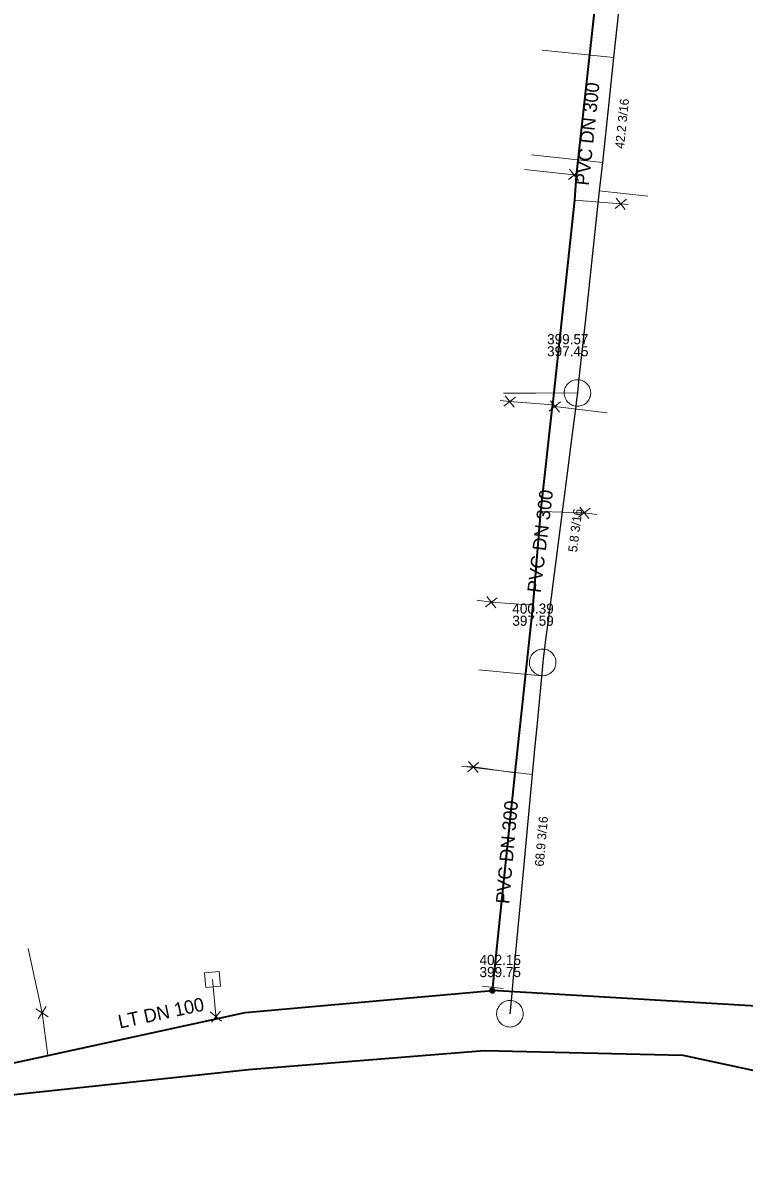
# Model space of a CAD drawing. Extents: x -772952 to -772403, y -1033777 to -1033210.
# Drawn here: x -772746.2 to -772682, y -1033603.9 to -1033502.9 of the extents above; entities that cross this region are included whole.
import ezdxf

# ---------------------------------------------------------------- set-up
doc = ezdxf.new("R2010")
doc.units = 0
doc.header["$LTSCALE"] = 0.36
for name, color, linetype, lineweight in [('15', 7, 'Continuous', 13), ('16', 7, 'Continuous', 35), ('2', 7, 'Continuous', 25), ('21', 7, 'Continuous', 13), ('4', 7, 'Continuous', 13), ('57', 7, 'Continuous', 13), ('59', 7, 'Continuous', 13)]:
    doc.layers.add(name, color=color, linetype=linetype, lineweight=lineweight)
for name, color, linetype in [('17', 7, 'Continuous'), ('3', 7, 'Continuous'), ('6', 7, 'Continuous')]:
    doc.layers.add(name, color=color, linetype=linetype)

msp = doc.modelspace()

# ---------------------------------------------------------------- linework, layer by layer
at = {"layer": '15'}
for p, q in [((-772696.643, -1033515.992), (-772697.658, -1033516.807)), ((-772696.747, -1033516.901), (-772697.552, -1033515.893)), ((-772693.507, -1033519.381), (-772692.502, -1033518.554)), ((-772693.414, -1033518.471), (-772692.596, -1033519.469)), ((-772702.369, -1033536.129), (-772703.392, -1033536.934)), ((-772702.482, -1033537.037), (-772703.278, -1033536.021)), ((-772699.365, -1033537.378), (-772698.344, -1033536.571)), ((-772699.254, -1033536.47), (-772698.456, -1033537.484)), ((-772696.757, -1033546.813), (-772695.726, -1033546.018)), ((-772696.635, -1033545.906), (-772695.85, -1033546.93)), ((-772703.991, -1033553.966), (-772705.024, -1033554.757)), ((-772704.116, -1033554.872), (-772704.898, -1033553.846)), ((-772705.61, -1033568.566), (-772706.589, -1033569.425)), ((-772705.675, -1033569.479), (-772706.523, -1033568.507)), ((-772703.459, -1033588.692), (-772705.309, -1033588.473)), ((-772743.894, -1033591.191), (-772744.987, -1033590.484)), ((-772744.79, -1033591.379), (-772744.087, -1033590.297)), ((-772728.485, -1033591.6), (-772729.487, -1033590.769)), ((-772729.396, -1033591.681), (-772728.57, -1033590.689))]:
    msp.add_line(p, q, dxfattribs=at)
for points in [[(-772704.19, -1033588.864), (-772704.196, -1033588.812), (-772704.213, -1033588.762), (-772704.242, -1033588.718), (-772704.279, -1033588.681), (-772704.324, -1033588.654), (-772704.374, -1033588.637), (-772704.427, -1033588.633), (-772704.478, -1033588.64), (-772704.527, -1033588.659), (-772704.571, -1033588.688), (-772704.607, -1033588.727), (-772704.633, -1033588.772), (-772704.649, -1033588.823), (-772704.652, -1033588.875), (-772704.644, -1033588.927), (-772704.624, -1033588.976), (-772704.593, -1033589.019), (-772704.554, -1033589.053), (-772704.508, -1033589.079), (-772704.456, -1033589.093), (-772704.404, -1033589.095), (-772704.353, -1033589.085), (-772704.304, -1033589.064), (-772704.262, -1033589.033), (-772704.228, -1033588.992), (-772704.204, -1033588.946), (-772704.191, -1033588.895)], [(-772704.22, -1033588.864), (-772704.226, -1033588.815), (-772704.243, -1033588.769), (-772704.271, -1033588.729), (-772704.308, -1033588.697), (-772704.352, -1033588.675), (-772704.4, -1033588.664), (-772704.449, -1033588.664), (-772704.495, -1033588.677), (-772704.539, -1033588.701), (-772704.575, -1033588.734), (-772704.602, -1033588.775), (-772704.618, -1033588.822), (-772704.622, -1033588.871), (-772704.615, -1033588.919), (-772704.596, -1033588.964), (-772704.566, -1033589.004), (-772704.527, -1033589.035), (-772704.483, -1033589.055), (-772704.436, -1033589.065), (-772704.387, -1033589.063), (-772704.34, -1033589.048), (-772704.297, -1033589.023), (-772704.262, -1033588.989), (-772704.237, -1033588.947), (-772704.223, -1033588.9)], [(-772704.25, -1033588.864), (-772704.255, -1033588.819), (-772704.272, -1033588.777), (-772704.301, -1033588.742), (-772704.337, -1033588.715), (-772704.379, -1033588.698), (-772704.424, -1033588.693), (-772704.468, -1033588.699), (-772704.51, -1033588.718), (-772704.544, -1033588.746), (-772704.571, -1033588.783), (-772704.588, -1033588.825), (-772704.592, -1033588.87), (-772704.585, -1033588.915), (-772704.566, -1033588.956), (-772704.537, -1033588.99), (-772704.5, -1033589.016), (-772704.456, -1033589.032), (-772704.412, -1033589.035), (-772704.367, -1033589.027), (-772704.326, -1033589.007), (-772704.293, -1033588.978), (-772704.267, -1033588.94), (-772704.253, -1033588.897)], [(-772704.28, -1033588.864), (-772704.284, -1033588.823), (-772704.303, -1033588.786), (-772704.33, -1033588.755), (-772704.365, -1033588.734), (-772704.405, -1033588.723), (-772704.446, -1033588.725), (-772704.485, -1033588.738), (-772704.519, -1033588.762), (-772704.544, -1033588.794), (-772704.559, -1033588.832), (-772704.561, -1033588.873), (-772704.554, -1033588.913), (-772704.534, -1033588.949), (-772704.505, -1033588.978), (-772704.468, -1033588.997), (-772704.428, -1033589.005), (-772704.387, -1033589.001), (-772704.348, -1033588.986), (-772704.316, -1033588.96), (-772704.294, -1033588.926), (-772704.281, -1033588.887)], [(-772704.309, -1033588.864), (-772704.315, -1033588.828), (-772704.333, -1033588.796), (-772704.358, -1033588.771), (-772704.392, -1033588.756), (-772704.429, -1033588.753), (-772704.463, -1033588.761), (-772704.495, -1033588.781), (-772704.517, -1033588.809), (-772704.531, -1033588.843), (-772704.531, -1033588.88), (-772704.52, -1033588.915), (-772704.499, -1033588.944), (-772704.468, -1033588.965), (-772704.434, -1033588.975), (-772704.397, -1033588.973), (-772704.363, -1033588.959), (-772704.336, -1033588.936), (-772704.316, -1033588.904), (-772704.309, -1033588.869)], [(-772704.34, -1033588.864), (-772704.345, -1033588.833), (-772704.362, -1033588.807), (-772704.387, -1033588.79), (-772704.418, -1033588.783), (-772704.449, -1033588.787), (-772704.476, -1033588.804), (-772704.494, -1033588.828), (-772704.502, -1033588.859), (-772704.498, -1033588.889), (-772704.483, -1033588.917), (-772704.458, -1033588.936), (-772704.429, -1033588.945), (-772704.397, -1033588.942), (-772704.37, -1033588.928), (-772704.35, -1033588.904), (-772704.34, -1033588.875)], [(-772704.37, -1033588.864), (-772704.375, -1033588.84), (-772704.392, -1033588.822), (-772704.414, -1033588.813), (-772704.439, -1033588.816), (-772704.46, -1033588.83), (-772704.471, -1033588.852), (-772704.471, -1033588.877), (-772704.458, -1033588.898), (-772704.439, -1033588.912), (-772704.414, -1033588.915), (-772704.391, -1033588.906), (-772704.375, -1033588.888)], [(-772704.4, -1033588.864), (-772704.405, -1033588.849), (-772704.419, -1033588.843), (-772704.434, -1033588.847), (-772704.441, -1033588.861), (-772704.438, -1033588.876), (-772704.424, -1033588.885), (-772704.409, -1033588.882), (-772704.4, -1033588.87)]]:
    msp.add_lwpolyline(points, close=True, dxfattribs=at)
at = {"layer": '16'}
msp.add_line((-772704.383, -1033588.583), (-772704.421, -1033588.864), dxfattribs=at)
for points in [[(-772704.383, -1033588.583), (-772702.394, -1033569.524), (-772700.793, -1033554.627), (-772700.105, -1033546.293), (-772699.07, -1033536.936), (-772699.052, -1033536.82), (-772697.087, -1033518.651), (-772696.925, -1033516.445), (-772694.923, -1033498.129)], [(-772871.839, -1033575.434), (-772870.427, -1033576.155), (-772849.008, -1033581.096), (-772841.55, -1033584.107), (-772822.87, -1033596.07), (-772815.517, -1033599.879), (-772800.324, -1033602.374), (-772785.625, -1033603.857), (-772759.69, -1033599.467), (-772726.1, -1033595.877), (-772705.133, -1033594.197), (-772687.467, -1033594.611), (-772649.087, -1033602.85)], [(-772759.272, -1033597.956), (-772743.932, -1033594.627), (-772726.379, -1033590.82), (-772704.421, -1033588.864)], [(-772638.76, -1033596.131), (-772655.276, -1033593.796), (-772676.921, -1033590.5), (-772704.421, -1033588.864)]]:
    msp.add_lwpolyline(points, dxfattribs=at)
at = {"layer": '2'}
for points in [[(-772691.61, -1033487.27), (-772691.649, -1033487.634), (-772691.677, -1033487.891), (-772691.701, -1033488.118), (-772691.747, -1033488.542), (-772692.035, -1033491.203), (-772692.309, -1033493.741), (-772693.008, -1033500.216), (-772693.63, -1033505.97), (-772694.06, -1033509.95), (-772694.633, -1033515.304), (-772694.908, -1033517.801), (-772695.388, -1033522.246), (-772696.055, -1033528.415), (-772696.596, -1033533.419), (-772696.742, -1033534.772), (-772696.85, -1033535.77)], [(-772696.85, -1033535.77), (-772696.902, -1033536.175), (-772696.961, -1033536.631), (-772697.003, -1033536.959), (-772697.141, -1033538.027), (-772697.469, -1033540.57), (-772697.77, -1033542.899), (-772698.506, -1033548.607), (-772699.46, -1033555.994), (-772699.675, -1033557.662), (-772699.776, -1033558.443), (-772699.839, -1033558.931), (-772699.863, -1033559.117), (-772699.94, -1033559.71)], [(-772699.94, -1033559.71), (-772700.444, -1033565.106), (-772700.66, -1033567.424), (-772700.869, -1033569.664), (-772701.647, -1033577.994), (-772702.461, -1033586.7), (-772702.748, -1033589.781), (-772702.855, -1033590.926)]]:
    msp.add_lwpolyline(points, dxfattribs=at)
at = {"layer": '21'}
msp.add_lwpolyline([(-772729.886, -1033588.595), (-772728.58, -1033588.473), (-772728.703, -1033587.167), (-772730.009, -1033587.289)], close=True, dxfattribs=at)
at = {"layer": '4'}
for points in [[(-772695.669, -1033535.77), (-772695.676, -1033535.651), (-772695.694, -1033535.534), (-772695.723, -1033535.418), (-772695.764, -1033535.307), (-772695.816, -1033535.2), (-772695.879, -1033535.099), (-772695.951, -1033535.004), (-772696.032, -1033534.918), (-772696.123, -1033534.84), (-772696.221, -1033534.771), (-772696.324, -1033534.713), (-772696.433, -1033534.666), (-772696.547, -1033534.629), (-772696.663, -1033534.604), (-772696.781, -1033534.592), (-772696.9, -1033534.591), (-772697.019, -1033534.602), (-772697.135, -1033534.625), (-772697.249, -1033534.659), (-772697.358, -1033534.705), (-772697.463, -1033534.762), (-772697.562, -1033534.829), (-772697.652, -1033534.905), (-772697.736, -1033534.99), (-772697.809, -1033535.084), (-772697.874, -1033535.184), (-772697.928, -1033535.29), (-772697.971, -1033535.401), (-772698.003, -1033535.515), (-772698.022, -1033535.633), (-772698.03, -1033535.752), (-772698.026, -1033535.87), (-772698.01, -1033535.988), (-772697.982, -1033536.104), (-772697.943, -1033536.216), (-772697.892, -1033536.324), (-772697.831, -1033536.426), (-772697.76, -1033536.522), (-772697.679, -1033536.609), (-772697.591, -1033536.689), (-772697.495, -1033536.759), (-772697.392, -1033536.819), (-772697.284, -1033536.868), (-772697.171, -1033536.906), (-772697.054, -1033536.932), (-772696.937, -1033536.947), (-772696.818, -1033536.95), (-772696.7, -1033536.941), (-772696.581, -1033536.92), (-772696.468, -1033536.887), (-772696.358, -1033536.843), (-772696.252, -1033536.788), (-772696.152, -1033536.722), (-772696.059, -1033536.647), (-772695.976, -1033536.563), (-772695.901, -1033536.471), (-772695.835, -1033536.372), (-772695.779, -1033536.267), (-772695.735, -1033536.157), (-772695.701, -1033536.043), (-772695.679, -1033535.926), (-772695.669, -1033535.807)], [(-772698.759, -1033559.71), (-772698.766, -1033559.591), (-772698.784, -1033559.474), (-772698.813, -1033559.358), (-772698.853, -1033559.247), (-772698.906, -1033559.14), (-772698.968, -1033559.039), (-772699.041, -1033558.944), (-772699.122, -1033558.858), (-772699.213, -1033558.78), (-772699.311, -1033558.711), (-772699.414, -1033558.653), (-772699.522, -1033558.606), (-772699.637, -1033558.569), (-772699.752, -1033558.544), (-772699.87, -1033558.532), (-772699.99, -1033558.531), (-772700.108, -1033558.542), (-772700.225, -1033558.565), (-772700.338, -1033558.599), (-772700.448, -1033558.645), (-772700.553, -1033558.702), (-772700.652, -1033558.769), (-772700.742, -1033558.845), (-772700.826, -1033558.93), (-772700.899, -1033559.024), (-772700.963, -1033559.124), (-772701.017, -1033559.23), (-772701.061, -1033559.341), (-772701.093, -1033559.455), (-772701.112, -1033559.573), (-772701.12, -1033559.692), (-772701.115, -1033559.81), (-772701.1, -1033559.928), (-772701.071, -1033560.044), (-772701.032, -1033560.156), (-772700.982, -1033560.264), (-772700.921, -1033560.366), (-772700.85, -1033560.462), (-772700.769, -1033560.549), (-772700.681, -1033560.629), (-772700.585, -1033560.699), (-772700.482, -1033560.759), (-772700.374, -1033560.808), (-772700.261, -1033560.846), (-772700.144, -1033560.872), (-772700.027, -1033560.887), (-772699.907, -1033560.89), (-772699.789, -1033560.881), (-772699.671, -1033560.86), (-772699.558, -1033560.827), (-772699.448, -1033560.783), (-772699.342, -1033560.728), (-772699.242, -1033560.662), (-772699.149, -1033560.587), (-772699.066, -1033560.503), (-772698.99, -1033560.411), (-772698.924, -1033560.312), (-772698.869, -1033560.207), (-772698.825, -1033560.097), (-772698.791, -1033559.983), (-772698.769, -1033559.866), (-772698.759, -1033559.747)], [(-772701.674, -1033590.926), (-772701.681, -1033590.807), (-772701.699, -1033590.69), (-772701.728, -1033590.574), (-772701.769, -1033590.463), (-772701.821, -1033590.356), (-772701.884, -1033590.255), (-772701.956, -1033590.16), (-772702.038, -1033590.074), (-772702.128, -1033589.996), (-772702.226, -1033589.927), (-772702.329, -1033589.869), (-772702.438, -1033589.822), (-772702.552, -1033589.785), (-772702.668, -1033589.76), (-772702.786, -1033589.748), (-772702.905, -1033589.747), (-772703.024, -1033589.758), (-772703.14, -1033589.781), (-772703.254, -1033589.815), (-772703.364, -1033589.861), (-772703.468, -1033589.918), (-772703.567, -1033589.985), (-772703.657, -1033590.061), (-772703.741, -1033590.146), (-772703.815, -1033590.24), (-772703.879, -1033590.34), (-772703.933, -1033590.446), (-772703.976, -1033590.557), (-772704.008, -1033590.671), (-772704.027, -1033590.789), (-772704.035, -1033590.908), (-772704.031, -1033591.026), (-772704.015, -1033591.144), (-772703.987, -1033591.26), (-772703.948, -1033591.372), (-772703.897, -1033591.48), (-772703.836, -1033591.582), (-772703.765, -1033591.678), (-772703.684, -1033591.765), (-772703.596, -1033591.845), (-772703.5, -1033591.915), (-772703.397, -1033591.975), (-772703.289, -1033592.024), (-772703.176, -1033592.062), (-772703.059, -1033592.088), (-772702.942, -1033592.103), (-772702.823, -1033592.106), (-772702.705, -1033592.097), (-772702.587, -1033592.076), (-772702.473, -1033592.043), (-772702.363, -1033591.999), (-772702.257, -1033591.944), (-772702.157, -1033591.878), (-772702.065, -1033591.803), (-772701.981, -1033591.719), (-772701.906, -1033591.627), (-772701.84, -1033591.528), (-772701.784, -1033591.423), (-772701.74, -1033591.313), (-772701.706, -1033591.199), (-772701.684, -1033591.082), (-772701.674, -1033590.963)]]:
    msp.add_lwpolyline(points, close=True, dxfattribs=at)
at = {"layer": '57'}
for p, q in [((-772693.63, -1033505.97), (-772699.98, -1033505.3)), ((-772694.633, -1033515.304), (-772700.92, -1033514.6)), ((-772694.908, -1033517.801), (-772690.59, -1033518.27)), ((-772700.051, -1033560.906), (-772705.61, -1033560.36)), ((-772700.869, -1033569.664), (-772706.64, -1033569))]:
    msp.add_line(p, q, dxfattribs=at)
msp.add_lwpolyline([(-772696.85, -1033535.77), (-772700.592, -1033535.784), (-772703.432, -1033535.795)], dxfattribs=at)
at = {"layer": '59'}
msp.add_line((-772728.967, -1033591.381), (-772729.295, -1033587.881), dxfattribs=at)
for points in [[(-772696.926, -1033516.446), (-772697.15, -1033516.399), (-772701.552, -1033515.918)], [(-772697.088, -1033518.651), (-772693.006, -1033518.969), (-772692.354, -1033519.032)], [(-772699.052, -1033536.821), (-772702.88, -1033536.531), (-772703.716, -1033536.432)], [(-772699.069, -1033536.936), (-772698.856, -1033536.976), (-772694.195, -1033537.521)], [(-772700.106, -1033546.294), (-772696.243, -1033546.417), (-772695.136, -1033546.56)], [(-772700.794, -1033554.628), (-772704.507, -1033554.361), (-772705.802, -1033554.19)], [(-772702.394, -1033569.525), (-772706.099, -1033568.995), (-772707.145, -1033568.927)], [(-772743.932, -1033594.627), (-772744.44, -1033590.84), (-772745.67, -1033585.12)]]:
    msp.add_lwpolyline(points, dxfattribs=at)

# ---------------------------------------------------------------- texts
at = {"layer": '17'}
msp.add_text('LT DN 100 ', height=1.2, rotation=12, dxfattribs=at).set_placement((-772737.537, -1033592.245))
at = {"layer": '3'}
for s, height, rotation, p in [('PVC DN 300', 1.2, 84, (-772695.841, -1033517.38)), ('42.2 3/16', 0.8, 84, (-772692.722, -1033514.095)), ('PVC DN 300', 1.2, 83, (-772700.126, -1033553.565)), ('5.8 3/16 ', 0.8, 83, (-772696.887, -1033549.948)), ('PVC DN 300', 1.2, 85, (-772702.923, -1033581.201)), ('68.9 3/16', 0.8, 85, (-772699.852, -1033577.871))]:
    msp.add_text(s, height=height, rotation=rotation, dxfattribs=at).set_placement(p)
at = {"layer": '6'}
for s, p in [('399.57', (-772699.548, -1033531.437)), ('397.45', (-772699.548, -1033532.514)), ('400.39', (-772702.638, -1033555.377)), ('397.59', (-772702.638, -1033556.454)), ('402.15', (-772705.554, -1033586.594)), ('399.75', (-772705.554, -1033587.671))]:
    msp.add_text(s, height=0.9, dxfattribs=at).set_placement(p)

doc.saveas('drawing.dxf')
